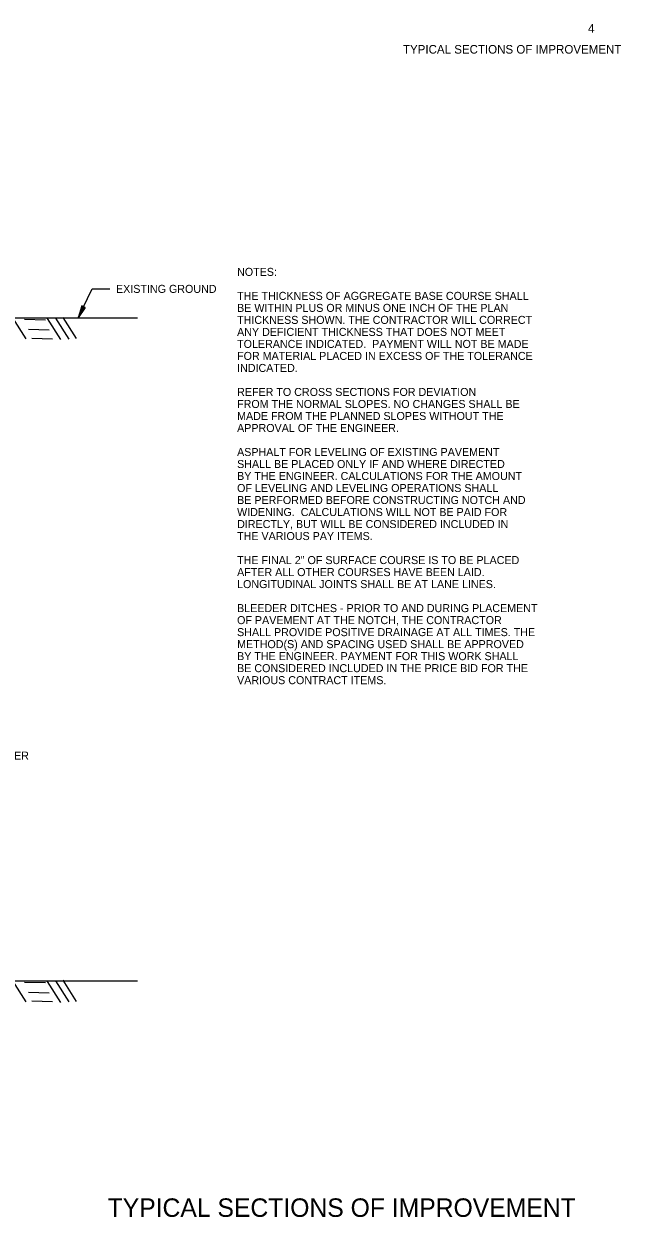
# Model space of a CAD drawing. Extents: x 6848689 to 6848907, y 1900908 to 1901005.
# Drawn here: x 6848782.6 to 6848831, y 1900907.7 to 1901004.6 of the extents above; entities that cross this region are included whole.
import ezdxf

# ---------------------------------------------------------------- set-up
doc = ezdxf.new("R2010")
doc.units = 0
for name, color, linetype in [('Default', 7, 'Continuous'), ('R_Dimension', 7, 'Continuous'), ('R_Draft', 7, 'Continuous'), ('R_No Plot', 7, 'Continuous')]:
    doc.layers.add(name, color=color, linetype=linetype)

msp = doc.modelspace()

# ---------------------------------------------------------------- linework, layer by layer
at = {"layer": 'Default'}
for p, q in [((6848778.354, 1900980.726), (6848791.788, 1900980.726)), ((6848778.354, 1900926.907), (6848791.788, 1900926.907))]:
    msp.add_line(p, q, dxfattribs=at)
at = {"layer": 'R_Draft'}
for p, q in [((6848788.103, 1900983.07), (6848789.526, 1900983.07)), ((6848787.261, 1900981.69), (6848786.956, 1900980.726)), ((6848787.53, 1900981.558), (6848786.956, 1900980.726)), ((6848787.283, 1900981.679), (6848787.029, 1900980.876)), ((6848787.508, 1900981.569), (6848787.029, 1900980.876)), ((6848787.306, 1900981.668), (6848787.105, 1900981.03)), ((6848787.485, 1900981.58), (6848787.105, 1900981.03)), ((6848787.329, 1900981.657), (6848787.178, 1900981.18)), ((6848787.462, 1900981.591), (6848787.178, 1900981.18)), ((6848787.351, 1900981.646), (6848787.253, 1900981.332)), ((6848787.439, 1900981.603), (6848787.253, 1900981.332)), ((6848787.53, 1900981.558), (6848787.261, 1900981.69)), ((6848787.374, 1900981.634), (6848787.326, 1900981.482)), ((6848787.417, 1900981.614), (6848787.326, 1900981.482))]:
    msp.add_line(p, q, dxfattribs=at)
at = {"layer": 'R_No Plot'}
for p, q in [((6848786.956, 1900980.726), (6848788.103, 1900983.07)), ((6848782.728, 1900979.014), (6848781.66, 1900980.722)), ((6848784.312, 1900980.546), (6848782.616, 1900980.591)), ((6848785.55, 1900978.957), (6848784.483, 1900980.665)), ((6848786.22, 1900979.004), (6848785.152, 1900980.711)), ((6848786.82, 1900979.052), (6848785.752, 1900980.76)), ((6848784.617, 1900979.728), (6848782.921, 1900979.773)), ((6848784.884, 1900979.008), (6848783.188, 1900979.054)), ((6848782.728, 1900925.195), (6848781.66, 1900926.903)), ((6848784.312, 1900926.727), (6848782.616, 1900926.772)), ((6848785.55, 1900925.138), (6848784.483, 1900926.846)), ((6848786.22, 1900925.185), (6848785.152, 1900926.892)), ((6848786.82, 1900925.233), (6848785.752, 1900926.941)), ((6848784.617, 1900925.909), (6848782.921, 1900925.954)), ((6848784.884, 1900925.189), (6848783.188, 1900925.235))]:
    msp.add_line(p, q, dxfattribs=at)

# ---------------------------------------------------------------- texts
at = {"layer": 'R_Dimension'}
for s, height, p in [('4', 0.722, (6848828.359, 1901003.872)), ('TYPICAL SECTIONS OF IMPROVEMENT', 1.5, (6848789.354, 1900907.734))]:
    msp.add_text(s, height=height, dxfattribs=at).set_placement(p)
msp.add_text('TYPICAL SECTIONS OF IMPROVEMENT', height=0.7, rotation=360, dxfattribs=at).set_placement((6848813.332, 1901002.177))
at = {"layer": 'R_Draft'}
for s, p in [('NOTES: ', (6848799.866, 1900984.134)), ('EXISTING GROUND', (6848790.035, 1900982.752)), ('THE THICKNESS OF AGGREGATE BASE COURSE SHALL', (6848799.866, 1900982.184)), ('BE WITHIN PLUS OR MINUS ONE INCH OF THE PLAN', (6848799.866, 1900981.209)), ('THICKNESS SHOWN. THE CONTRACTOR WILL CORRECT', (6848799.866, 1900980.234)), ('ANY DEFICIENT THICKNESS THAT DOES NOT MEET', (6848799.866, 1900979.259)), ('TOLERANCE INDICATED.  PAYMENT WILL NOT BE MADE', (6848799.866, 1900978.284)), ('FOR MATERIAL PLACED IN EXCESS OF THE TOLERANCE', (6848799.866, 1900977.309)), ('INDICATED.', (6848799.866, 1900976.334)), ('REFER TO CROSS SECTIONS FOR DEVIATION', (6848799.866, 1900974.384)), ('FROM THE NORMAL SLOPES. NO CHANGES SHALL BE', (6848799.866, 1900973.409)), ('MADE FROM THE PLANNED SLOPES WITHOUT THE ', (6848799.866, 1900972.434)), ('APPROVAL OF THE ENGINEER.', (6848799.866, 1900971.459)), ('ASPHALT FOR LEVELING OF EXISTING PAVEMENT', (6848799.866, 1900969.509)), ('SHALL BE PLACED ONLY IF AND WHERE DIRECTED ', (6848799.866, 1900968.534)), ('BY THE ENGINEER. CALCULATIONS FOR THE AMOUNT', (6848799.866, 1900967.559)), ('OF LEVELING AND LEVELING OPERATIONS SHALL', (6848799.866, 1900966.584)), ('BE PERFORMED BEFORE CONSTRUCTING NOTCH AND ', (6848799.866, 1900965.609)), ('WIDENING.  CALCULATIONS WILL NOT BE PAID FOR', (6848799.866, 1900964.634)), ('DIRECTLY, BUT WILL BE CONSIDERED INCLUDED IN', (6848799.866, 1900963.659)), ('THE VARIOUS PAY ITEMS.    ', (6848799.866, 1900962.684)), ('THE FINAL 2" OF SURFACE COURSE IS TO BE PLACED ', (6848799.866, 1900960.734)), ('AFTER ALL OTHER COURSES HAVE BEEN LAID. ', (6848799.866, 1900959.759)), ('LONGITUDINAL JOINTS SHALL BE AT LANE LINES.', (6848799.866, 1900958.784)), ('BLEEDER DITCHES - PRIOR TO AND DURING PLACEMENT', (6848799.866, 1900956.834)), ('OF PAVEMENT AT THE NOTCH, THE CONTRACTOR', (6848799.866, 1900955.859)), ('SHALL PROVIDE POSITIVE DRAINAGE AT ALL TIMES. THE', (6848799.866, 1900954.884)), ('METHOD(S) AND SPACING USED SHALL BE APPROVED', (6848799.866, 1900953.909)), ('BY THE ENGINEER. PAYMENT FOR THIS WORK SHALL ', (6848799.866, 1900952.934)), ('BE CONSIDERED INCLUDED IN THE PRICE BID FOR THE', (6848799.866, 1900951.959)), ('VARIOUS CONTRACT ITEMS.', (6848799.866, 1900950.984)), ('DIRECTED BY THE ENGINEER', (6848770.36, 1900944.858))]:
    msp.add_text(s, height=0.65, dxfattribs=at).set_placement(p)

doc.saveas('drawing.dxf')
